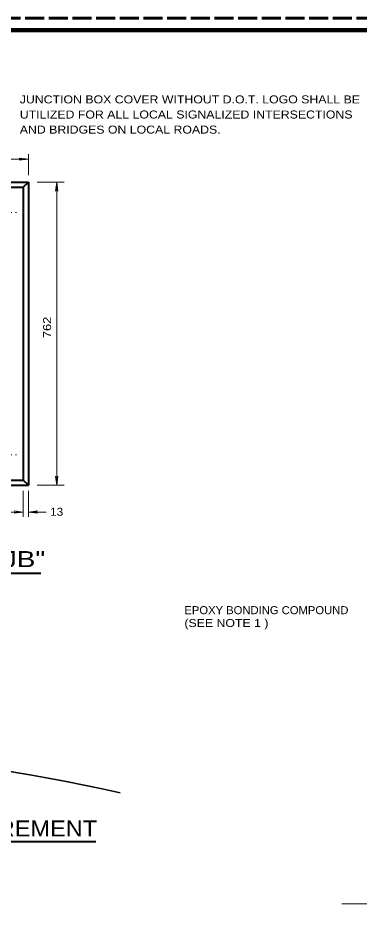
# Model space of a CAD drawing. Extents: x 312583 to 312853, y 144419 to 144586.
# Drawn here: x 312766 to 312798.5, y 144499.9 to 144586.2 of the extents above; entities that cross this region are included whole.
import ezdxf
from ezdxf.enums import TextEntityAlignment as Align

# ---------------------------------------------------------------- set-up
doc = ezdxf.new("R2010")
doc.units = 0
doc.header["$LTSCALE"] = 0.3
doc.linetypes.add('DOTTED', pattern=[1.5, 0.3, -1.2])
doc.linetypes.add('LONG_DASHED', pattern=[7.5, 6, -1.5])
doc.layers.add('1', color=7, linetype='Continuous', lineweight=40)
doc.layers.add('2', color=7, linetype='Continuous', lineweight=13)

msp = doc.modelspace()

# ---------------------------------------------------------------- linework, layer by layer
at = {"layer": '1', "linetype": 'LONG_DASHED', "lineweight": 60}
msp.add_line((312851.75, 144586.2246), (312583.526, 144586.2246), dxfattribs=at)
msp.add_line((312851.75, 144586.2246), (312583.526, 144586.2246), dxfattribs=at)
at = {"layer": '1'}
for p, q in [((312721.0054, 144570.6589), (312767.0054, 144570.6589)), ((312766.5224, 144570.1759), (312767.0054, 144570.6589)), ((312767.0054, 144570.6589), (312767.0054, 144541.9089)), ((312721.0054, 144541.9089), (312767.0054, 144541.9089)), ((312721.4807, 144542.3842), (312766.5224, 144542.3842)), ((312767.0054, 144541.9089), (312766.5224, 144542.3842)), ((312721.3052, 144508.0989), (312773.4318, 144508.0989))]:
    msp.add_line(p, q, dxfattribs=at)
at = {"layer": '1', "lineweight": 158}
msp.add_lwpolyline([(312616.5, 144423.1446), (312616.5, 144585.0846), (312849, 144585.0846)], dxfattribs=at)
at = {"layer": '1'}
msp.add_lwpolyline([(312721.4807, 144570.1759), (312766.5224, 144570.1759), (312766.5224, 144542.3842)], dxfattribs=at)
at = {"layer": '1', "lineweight": 35}
msp.add_arc((312731.3674, 144313.1134), 204.4606, 77.47167, 93.11775, dxfattribs=at)
at = {"layer": '2'}
for p, q in [((312721.0054, 144572.8439), (312767.0054, 144572.8439)), ((312766.139, 144572.9512), (312766.415, 144572.8439)), ((312767.0054, 144572.8439), (312766.139, 144572.9512)), ((312766.139, 144572.7366), (312766.415, 144572.8439)), ((312767.0054, 144572.8439), (312766.139, 144572.7366)), ((312767.0054, 144571.3336), (312767.0054, 144573.3346)), ((312767.841, 144570.6589), (312770.394, 144570.6589)), ((312769.704, 144570.6589), (312769.5967, 144569.7926)), ((312769.704, 144541.9089), (312769.704, 144570.6589)), ((312769.704, 144570.6589), (312769.8114, 144569.7926)), ((312769.5967, 144569.7926), (312769.704, 144570.0686)), ((312769.8114, 144569.7926), (312769.704, 144570.0686)), ((312769.5967, 144542.7752), (312769.704, 144542.4992)), ((312769.704, 144541.9089), (312769.5967, 144542.7752)), ((312769.8114, 144542.7752), (312769.704, 144542.4992)), ((312769.704, 144541.9089), (312769.8114, 144542.7752)), ((312767.841, 144541.9089), (312770.394, 144541.9089)), ((312766.5224, 144541.3646), (312766.5224, 144538.8959)), ((312767.0054, 144541.3646), (312767.0054, 144538.8959)), ((312764.414, 144539.3559), (312766.5224, 144539.3559)), ((312766.5224, 144539.3559), (312765.656, 144539.4632)), ((312766.5224, 144539.3559), (312765.656, 144539.2486)), ((312767.0054, 144539.3559), (312767.8717, 144539.4632)), ((312767.0054, 144539.3559), (312768.7074, 144539.3559)), ((312767.0054, 144539.3559), (312767.8717, 144539.2486)), ((312767.8717, 144539.4632), (312767.5957, 144539.3559)), ((312767.8717, 144539.2486), (312767.5957, 144539.3559)), ((312796.8166, 144502.1841), (312815.8759, 144502.1841))]:
    msp.add_line(p, q, dxfattribs=at)
at = {"layer": '2', "linetype": 'DOTTED'}
for p, q in [((312764.3987, 144567.7839), (312766.1927, 144567.7839)), ((312764.3987, 144544.7839), (312766.1927, 144544.7839))]:
    msp.add_line(p, q, dxfattribs=at)
at = {"layer": '2', "lineweight": 40}
msp.add_line((312722.5394, 144533.5554), (312768.1782, 144533.5554), dxfattribs=at)

# ---------------------------------------------------------------- texts
at = {"layer": '1', "width": 1.1}
msp.add_text('BREAKAWAY SUPPORT HEIGHT MEASUREMENT', height=1.52, dxfattribs=at).set_placement((312747.2009, 144508.5649), align=Align.CENTER)
at = {"layer": '2'}
for s, width, p in [('JUNCTION BOX COVER WITHOUT D.O.T. LOGO SHALL BE', 1.15, (312766.1892, 144578.1377)), ('UTILIZED FOR ALL LOCAL SIGNALIZED INTERSECTIONS', 1.15, (312766.1892, 144576.704)), ('AND BRIDGES ON LOCAL ROADS.', 1.15, (312766.1892, 144575.2703)), ('13 ', 1.1, (312769.0719, 144539.0016)), ('EPOXY BONDING COMPOUND', 1.05, (312781.8358, 144529.6627)), ('(SEE NOTE 1 )', 1.15, (312781.8358, 144528.4427))]:
    msp.add_text(s, height=0.76, dxfattribs=dict(at, width=width)).set_placement(p)
at = {"layer": '2', "width": 1.2}
msp.add_text('762 ', height=0.76, rotation=90, dxfattribs=at).set_placement((312769.1632, 144555.8607))
at = {"layer": '2', "width": 1.3}
msp.add_text('450 BY 900 MM JUNCTION BOX - "JB"', height=1.52, dxfattribs=at).set_placement((312745.2779, 144534.1286), align=Align.CENTER)

doc.saveas('drawing.dxf')
